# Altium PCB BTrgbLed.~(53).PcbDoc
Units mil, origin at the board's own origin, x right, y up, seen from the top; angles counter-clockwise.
Board outline 3886.28 x 3884.79 mil, 2 copper layers (Top Layer, Bottom Layer); 15 components, 12 nets, 66 pads, 4 vias.
Unrouted connection lines stored in the file: 34.
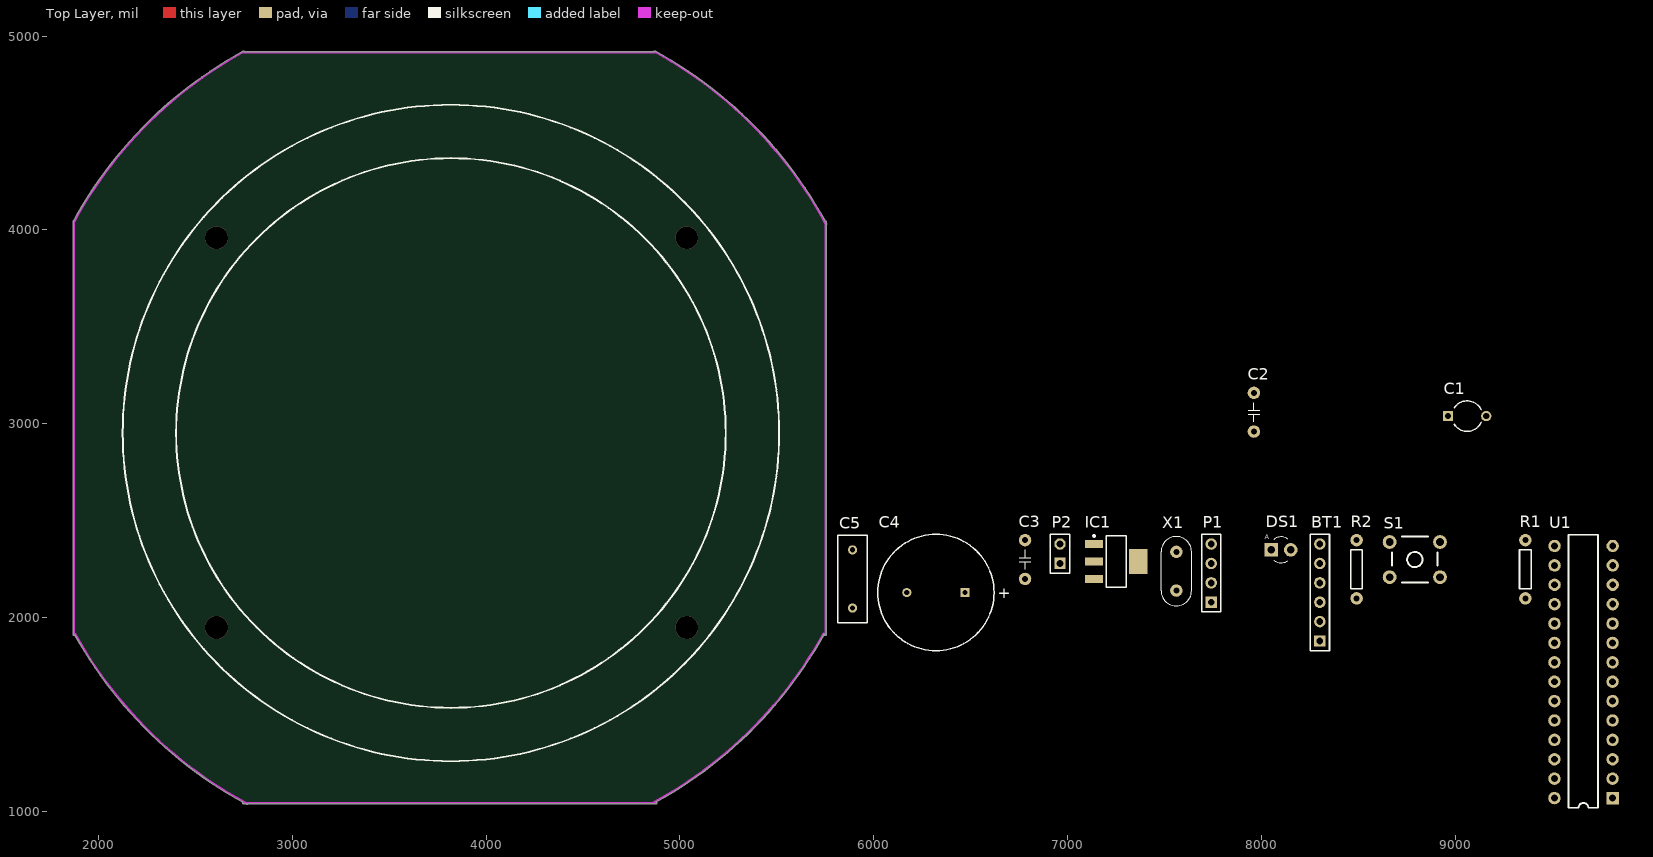
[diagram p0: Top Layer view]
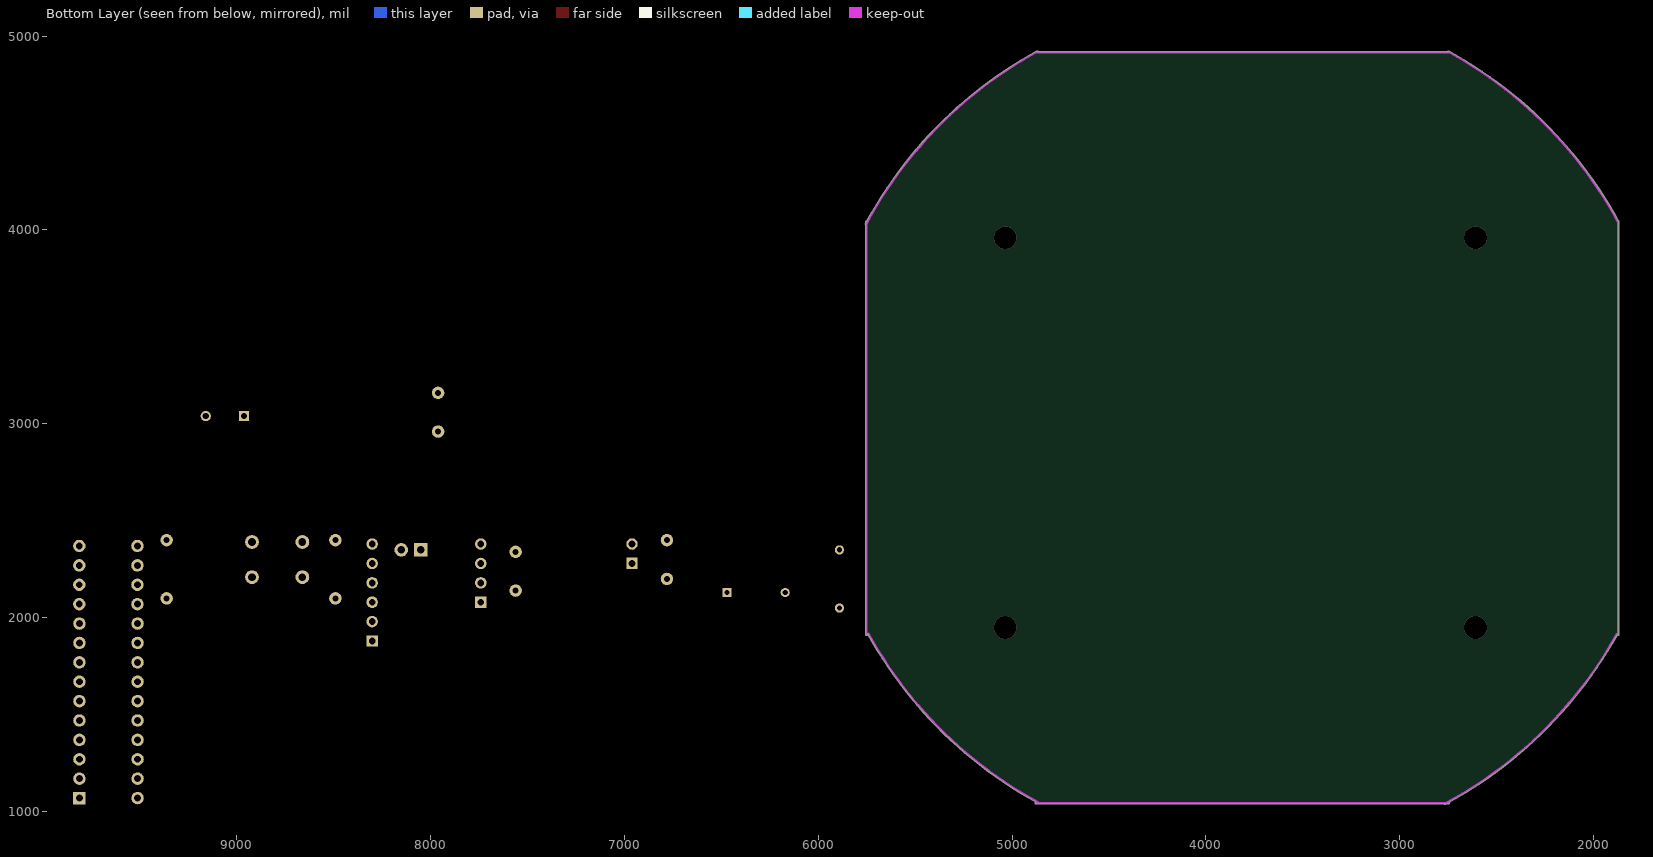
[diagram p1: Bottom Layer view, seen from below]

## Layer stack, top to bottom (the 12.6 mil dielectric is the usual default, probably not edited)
Top Layer: signal copper 1.4
Dielectric: dielectric 12.6, FR-4, Dk 4.8
Bottom Layer: signal copper 1.4

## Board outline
2750,1039.98 2761.53,1039.98 ccw(c3810.28,2985) 2764.5,1038.38 ccw(c2766.88,1042.8) 2771.03,1039.98 4875.98,1039.98 ccw(c4875.98,1045) 4881,1045 ccw(c4875.98,1045) 4877.16,1049.88 ccw(c3810.28,2985) 5744.74,1916.92 ccw(c5740.35,1919.34) 5744.98,1917.43 5744.98,1914.02 ccw(c5750,1914.02) 5755.02,1914.02 5755.02,4027.36 ccw(c5751.25,4030.67) 5756.26,4030.67 ccw(c5751.25,4030.67) 5755.66,4033.05 ccw(c3810.28,2985) 5755.02,4034.26 5755.02,4040 ccw(c5750,4040) 5749.21,4044.95 ccw(c3810.28,2985) 4873.82,4921.96 ccw(c4871.41,4917.56) 4867.03,4920.02 2752.96,4920.02 ccw(c2748.72,4917.33) 2746.3,4921.73 ccw(c3810.28,2985) 1872.41,4046.9 ccw(c1876.81,4044.49) 1871.83,4043.89 ccw(c1875,4040) 1869.98,4040 1869.98,1914.02 ccw(c1875,1914.02) 1879.06,1911.07 ccw(c3810.28,2985) 2746.23,1048.31 ccw(c2750,1045)

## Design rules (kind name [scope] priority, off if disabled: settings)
Clearance 舖銅安全間距 [All] p1: gap=25
Clearance [All] p2: gap=10
PolygonConnect [All] p1: connectstyle=Relief reliefconductorwidth=10 reliefentries=4 polygonreliefangle="90 Angle"
RoomDefinition BTrgbLed [InComponentClass('BTrgbLed')] p1: confinementstyle=ConfineIn formatcopy=TRUE lockcomponents=FALSE outline 5800,1010 9860,1010 9860,2550 5800,2550
RoutingLayers [All] p1: top layer_v5=FALSE bottom layer_v5=TRUE
RoutingVias [All] p1: holewidth=28 width=50 viastyle="Through Hole" minholewidth=28 minwidth=50 maxholewidth=28 maxwidth=50
SilkscreenOverComponentPads [All] p1: minsilkscreentomaskgap=10
SolderMaskExpansion [All] p1: expansion=4
Width [All] p1: maxlimit=40 minlimit=20 preferedwidth=30
26 further rules are at their usual default settings.

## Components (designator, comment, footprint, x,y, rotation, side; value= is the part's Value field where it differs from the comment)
BT1 "Bluetooth" Bluetooth 8300,1880 r90 top
C1 "Cap2" CAPR5-4X5 9060,3040 r0 top
C2 "22pF" C200 7960,3060 r0 top
C3 "22pF" C200 6780,2300 r0 top
C4 "47uF" RB7.6-15 6320,2130 r0 top
C5 "Cap" RAD-0.3 5890,2200 r90 top
DS1 "TX-LED" LED-3mm_G 8100,2350 r0 top
IC1 "AM1117-5V" SOT-223 7250,2290 r0 top
P1 "環形LED燈" HDR1X4 7740,2080 r90 top
P2 "12V" HDR1X2 6960,2280 r90 top
R1 "10k" AXIAL-0.3 9360,2250 r90 top
R2 "220" AXIAL-0.3 8490,2250 r90 top
S1 "SW-PB" TACK6 8790,2300 r0 top
U1 "ATmega328" DIP-28 9810,1070 r90 top
X1 "16MHz" XTAL4-8 7560,2240 r90 top

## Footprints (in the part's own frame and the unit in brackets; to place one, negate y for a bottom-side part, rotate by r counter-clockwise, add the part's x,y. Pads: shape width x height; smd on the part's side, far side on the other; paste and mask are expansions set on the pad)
AXIAL-0.3 [mil] "0.3\" Resistor; 2 Leads"
  round 64 hole 31.5: 1(-150,0) 2(150,0)
  silkscreen extent -100,-30 100,30, body extent -161,-39 165,39, height 86
Bluetooth [mm]
  rect 1.5x1.5 hole 0.9: 1(0,0)
  round 1.5 hole 0.9: 2(2.54,0) 3(5.08,0) 4(7.62,0) 5(10.16,0) 6(12.7,0)
  silkscreen extent -1.27,-1.27 13.97,1.27, body extent -1.25,-1.3 13.97,1.28, height 11
C200 [mil] "塑膠電容器"
  round 64 hole 31.5: 1(0,100) 2(0,-100)
  silkscreen extent -30,-50 30,50, body extent -41,-136 39,135, height 354
CAPR5-4X5 [mm] "Capacitor; 2 Leads"
  rect 1.35x1.35 hole 0.8: 1(-2.5,0)
  round 1.35 hole 0.8: 2(2.5,0)
  silkscreen extent -1.69,-2 1.82,2
DIP-28 [mil]
  rect 64x64 hole 35.43: 1(0,0)
  round 64 hole 35.43: 2(100,0) 3(200,0) 4(300,0) 5(400,0) 6(500,0) 7(600,0) 8(700,0) 9(800,0) 10(900,0) 11(1000,-0.79) 12(1100,-0.79) 13(1200,-0.79) 14(1300,-0.79) 15(1300,299.21) 16(1200,299.21) 17(1100,299.21) 18(1000,299.21) 19(900,300) 20(800,300) 21(700,300) 22(600,300) 23(500,300) 24(400,300) 25(300,300) 26(200,300) 27(100,300) 28(0,300)
  silkscreen extent -50,74 1358,228, body extent -53,-5 1358,304, height 209
HDR1X2 [mm] "Connector; Header; 2 Position"
  rect 1.5x1.5 hole 0.9: 1(0,0)
  round 1.5 hole 0.9: 2(2.54,0)
  silkscreen extent -1.27,-1.27 3.81,1.27
HDR1X4 [mm] "Connector; Header; 4 Position"
  rect 1.5x1.5 hole 0.9: 1(0,0)
  round 1.5 hole 0.9: 2(2.54,0) 3(5.08,0) 4(7.62,0)
  silkscreen extent -1.27,-1.27 8.89,1.27
LED-3mm_G [mil] "3mm LED_Green"
  rect 70x70 hole 39: 1(-50,0)
  round 70 hole 39: 2(50,0)
  silkscreen extent -38,-67 35,67, body extent -66,-68 67,66, height 181
RAD-0.3 [mm] "Radial Cap, Thru-Hole; 2 Leads; 0.3 in Pin Spacing"
  round 1.2 hole 0.7: 1(-3.81,0) 2(3.81,0)
  silkscreen extent -5.71,-1.91 5.71,1.91
RB7.6-15 [mm] "Polarized Capacitor (Radial); 2 Leads"
  rect 1.2x1.2 hole 0.7: 1(3.81,0)
  round 1.2 hole 0.7: 2(-3.81,0)
  silkscreen extent -7.62,-7.62 7.62,7.62
SOT-223 [mm] "SOT223, 4-Leads, Body 6.7x7.3mm (max), Pitch 2.30mm, IPC Medium Density"
  rect 2.4x1 smd: 1(-2.9,2.3) 2(-2.9,0) 3(-2.9,-2.3)
  rect 2.4x3.3 smd: 2(2.9,0)
  silkscreen extent -3.02,-3.35 1.3,3.47, body extent -1.86,-3.35 1.86,3.35, height 1.8
TACK6 [mm]
  round 1.8 hole 1: 1(-3.3,2.3) 1(3.3,2.3) 2(-3.3,-2.3) 2(3.3,-2.3)
  silkscreen extent -3,-3 3,3, body extent -3,-3.01 3.08,3.04, height 8
XTAL4-8 [mil]
  round 64 hole 31.5: 1(-100,0) 2(100,0)
  silkscreen extent -179,-79 179,79, body extent -178,-80 192,79, height 157

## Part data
C1 C5: "Capacitor"
C2 C3: library part Cap, "Capacitor"
C4: library part "Cap Pol1", "Polarized Capacitor (Radial)"
DS1: library part LED, "Typical INFRARED GaAs LED"
IC1: library part AM1117
P1: library part "Header 4", "Header, 4-Pin"
P2: library part "Header 2", "Header, 2-Pin"
R1 R2: library part Res, "Resistor"
S1: "Switch"
U1: "Arduino"
X1: library part XTAL, "Crystal Oscillator"

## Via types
v1: diameter 118.11, hole 118.11, Top Layer to Bottom Layer, 4 vias

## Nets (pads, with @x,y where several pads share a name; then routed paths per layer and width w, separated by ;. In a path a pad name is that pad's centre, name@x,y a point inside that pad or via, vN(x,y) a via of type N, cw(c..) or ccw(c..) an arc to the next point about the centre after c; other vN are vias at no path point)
DI: P1.1 U1.12
DO: P1.4
GND: BT1.3 C1.2 C3.1 C4.2 C5.2 DS1.2 IC1.1 P1.3 P2.2 S1.1 U1.8 U1.22
NetC1_1: C1.1 R1.2 S1.2 U1.1
NetC2_2: C2.2 U1.10 X1.2
NetC3_2: C3.2 U1.9 X1.1
NetDS1_1: DS1.1 R2.1
NetIC1_3: IC1.3 P2.1
NetR2_2: R2.2 U1.19
RX: BT1.5 U1.6
TX: BT1.4 U1.5
VCC: BT1.2 C4.1 C5.1 IC1.2 P1.2 R1.1 U1.7 U1.20
pads on no net: BT1.1 BT1.6 C2.1 U1.2 U1.3 U1.4 U1.11 U1.13 U1.14 U1.15 U1.16 U1.17 U1.18 U1.21 U1.23 U1.24 U1.25 U1.26 U1.27 U1.28
copper on no net:
  other v1: 2610,1950 5035,1950 2610,3960 5035,3960

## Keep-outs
Keep-Out Layer:
  lines w10: 1875,1914.02 1875,4040 ; 1876.81,4044.49 cw(c3810.28,2985) 2748.72,4917.33 ; 1881.24,1917.47 ccw(c3810.28,2985) 2766.88,1042.8 ; 2750,1045 4875.98,1045 ; 2750,4915 4875.98,4915 ; 4865.51,1049.21 ccw(c3810.28,2985) 5740.35,1919.34 ; 4871.41,4917.56 cw(c3810.28,2985) 5751.25,4030.67 ; 5750,1914.02 5750,4040

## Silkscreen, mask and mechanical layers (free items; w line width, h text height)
Top Overlay:
  circle w10: c3818.9,2952.76 r1417.32
  circle w10: c3818.9,2952.76 r1692.91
